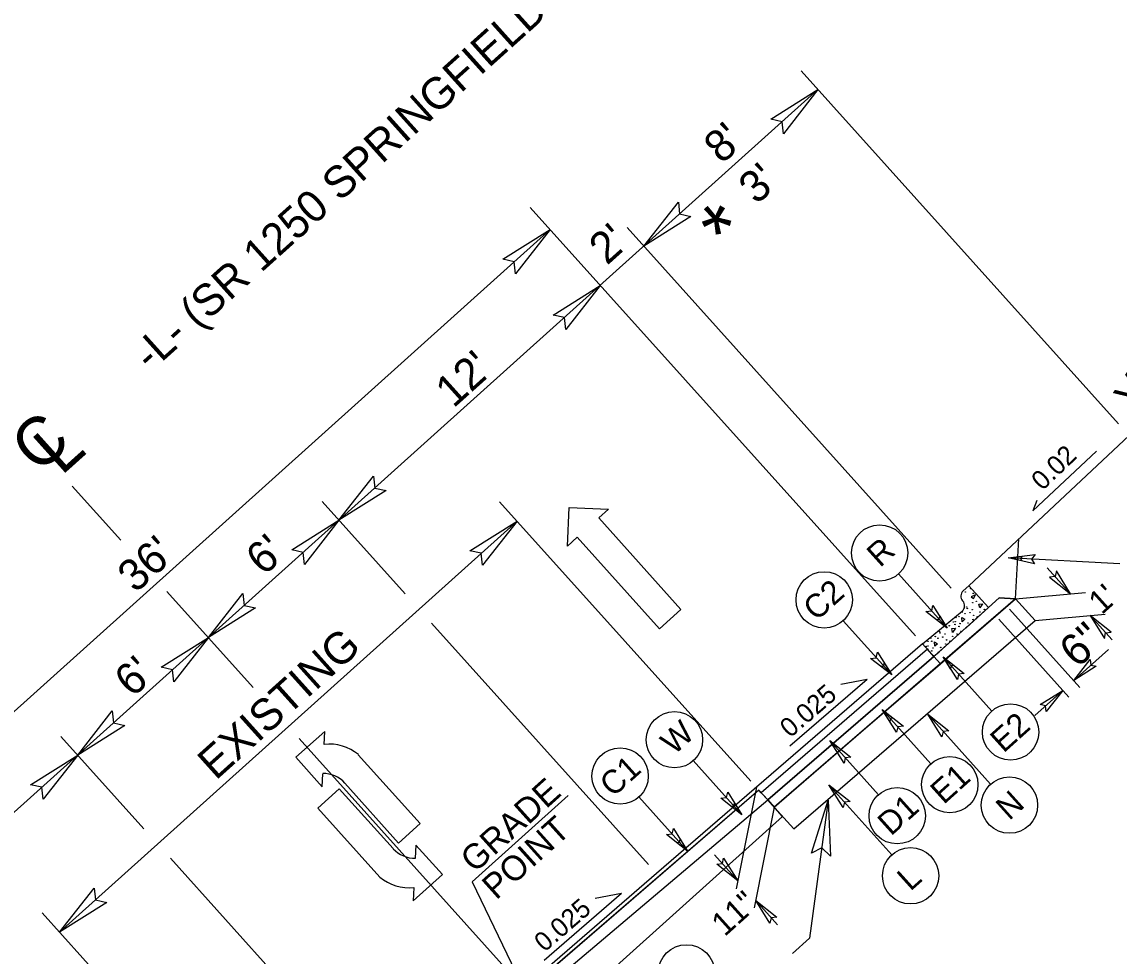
# Model space of a CAD drawing. Extents: x 2488411 to 2488707, y 383669 to 383962.
# Drawn here: x 2488564.63 to 2488602.08, y 383868.92 to 383900.82 of the extents above; entities that cross this region are included whole.
import ezdxf

# ---------------------------------------------------------------- set-up
doc = ezdxf.new("R2010")
doc.units = 0
for name, color, linetype in [('Old_Level_44', 7, 'Continuous'), ('Prop Dimension', 7, 'Continuous'), ('Prop DSN Text', 7, 'Continuous'), ('Prop Paint Stripe', 7, 'Continuous'), ('Prop PFL Text', 7, 'Continuous'), ('Prop Rip Rap Related Quantities Text', 7, 'Continuous'), ('Prop Roadway Profile Bench Mark Info Text', 7, 'Continuous'), ('Prop ROW RW Lines', 7, 'Continuous'), ('Prop Vertical Profile Curve Label', 7, 'Continuous'), ('Sheet Data Field CELL', 7, 'Continuous'), ('Sheet Sticker Preliminary CELL', 7, 'Continuous'), ('Sheet Symbology CELL', 7, 'Continuous'), ('Sheet Title CELL', 7, 'Continuous'), ('Typical Hinge Slope Arterial CELL', 7, 'Continuous'), ('Typical ID Circle CELL', 7, 'Continuous'), ('Typical Terminator CELL', 7, 'Continuous'), ('Typical Text ID Circle CELL', 7, 'Continuous')]:
    doc.layers.add(name, color=color, linetype=linetype)

msp = doc.modelspace()

# ---------------------------------------------------------------- linework, layer by layer
at = {"layer": 'Prop Dimension'}
for p, q in [((2488580.003, 383871.462), (2488583.276, 383874.404)), ((2488592.155, 383874.246), (2488591.519, 383869.531)), ((2488580.003, 383871.462), (2488581.754, 383867.821)), ((2488590.941, 383869.012), (2488591.519, 383869.531))]:
    msp.add_line(p, q, dxfattribs=at)
at = {"layer": 'Prop DSN Text'}
for p, q in [((2488602.106, 383882.32), (2488598.304, 383882.521)), ((2488594.554, 383881.97), (2488596.216, 383880.122)), ((2488592.662, 383880.369), (2488594.324, 383878.521)), ((2488597.739, 383877.287), (2488596.078, 383879.135)), ((2488595.662, 383875.49), (2488594.001, 383877.338)), ((2488597.699, 383874.791), (2488595.552, 383877.179)), ((2488593.87, 383874.429), (2488592.208, 383876.278)), ((2488587.549, 383875.594), (2488589.21, 383873.746)), ((2488594.325, 383872.379), (2488592.178, 383874.767)), ((2488585.692, 383874.355), (2488587.354, 383872.507))]:
    msp.add_line(p, q, dxfattribs=at)
for centre in [(2488593.911, 383882.685), (2488592.019, 383881.084), (2488586.906, 383876.309), (2488598.382, 383876.572), (2488585.049, 383875.07), (2488596.305, 383874.775), (2488598.342, 383874.076), (2488594.512, 383873.714), (2488594.968, 383871.664), (2488587.314, 383868.347)]:
    msp.add_circle(centre, 0.962, dxfattribs=at)
at = {"layer": 'Prop Paint Stripe'}
for points in [[(2488599.194, 383882.319), (2488598.304, 383882.521), (2488599.216, 383882.633), (2488599.093, 383882.479)], [(2488599.713, 383881.858), (2488600.43, 383881.292), (2488599.944, 383882.072), (2488599.902, 383881.88)], [(2488595.729, 383880.895), (2488596.216, 383880.122), (2488595.492, 383880.688), (2488595.687, 383880.709)], [(2488601.816, 383879.983), (2488601.099, 383880.548), (2488601.585, 383879.768), (2488601.627, 383879.961)], [(2488593.837, 383879.294), (2488594.324, 383878.521), (2488593.6, 383879.087), (2488593.795, 383879.108)], [(2488596.564, 383878.362), (2488596.078, 383879.135), (2488596.802, 383878.569), (2488596.606, 383878.548)], [(2488601.309, 383878.815), (2488600.536, 383878.329), (2488601.102, 383879.053), (2488601.124, 383878.857)], [(2488599.391, 383877.508), (2488600.164, 383877.995), (2488599.598, 383877.271), (2488599.577, 383877.466)], [(2488594.487, 383876.565), (2488594.001, 383877.338), (2488594.725, 383876.772), (2488594.529, 383876.751)], [(2488596.039, 383876.406), (2488595.552, 383877.179), (2488596.276, 383876.613), (2488596.08, 383876.591)], [(2488592.695, 383875.505), (2488592.208, 383876.278), (2488592.932, 383875.712), (2488592.736, 383875.69)], [(2488592.665, 383873.994), (2488592.178, 383874.767), (2488592.902, 383874.201), (2488592.706, 383874.18)], [(2488588.724, 383874.519), (2488589.21, 383873.746), (2488588.486, 383874.312), (2488588.682, 383874.333)], [(2488586.867, 383873.28), (2488587.354, 383872.507), (2488586.63, 383873.073), (2488586.826, 383873.095)], [(2488588.585, 383872.266), (2488589.071, 383871.493), (2488588.347, 383872.059), (2488588.543, 383872.081)], [(2488590.166, 383870.043), (2488589.68, 383870.816), (2488590.404, 383870.25), (2488590.208, 383870.229)]]:
    msp.add_lwpolyline(points, close=True, dxfattribs=at)
at = {"layer": 'Prop PFL Text'}
for p, q in [((2488599.144, 383884.129), (2488601.311, 383886.159)), ((2488599.279, 383884.472), (2488599.144, 383884.129))]:
    msp.add_line(p, q, dxfattribs=at)
at = {"layer": 'Prop Rip Rap Related Quantities Text'}
for p, q in [((2488598.554, 383881.124), (2488598.663, 383883.163)), ((2488598.554, 383881.124), (2488590.312, 383874.008)), ((2488597.996, 383881.154), (2488597.625, 383880.82)), ((2488597.996, 383881.154), (2488598.554, 383881.124)), ((2488598.554, 383881.124), (2488599.223, 383880.381)), ((2488590.981, 383873.264), (2488599.223, 383880.381)), ((2488595.376, 383879.582), (2488586.294, 383871.741)), ((2488595.543, 383879.396), (2488589.871, 383874.499)), ((2488595.764, 383879.151), (2488590.091, 383874.253)), ((2488595.766, 383879.149), (2488595.984, 383878.905)), ((2488589.787, 383874.592), (2488581.836, 383867.727)), ((2488590.091, 383874.253), (2488589.787, 383874.592)), ((2488590.312, 383874.008), (2488590.981, 383873.264)), ((2488586.294, 383871.741), (2488581.754, 383867.821))]:
    msp.add_line(p, q, dxfattribs=at)
at = {"layer": 'Prop Roadway Profile Bench Mark Info Text'}
for p, q in [((2488593.48, 383878.37), (2488590.84, 383876.091)), ((2488593.48, 383878.37), (2488592.581, 383878.198)), ((2488585.092, 383871.053), (2488582.452, 383868.775)), ((2488585.092, 383871.053), (2488584.193, 383870.882))]:
    msp.add_line(p, q, dxfattribs=at)
at = {"layer": 'Prop ROW RW Lines'}
for p, q in [((2488583.248, 383882.919), (2488583.308, 383884.244)), ((2488583.308, 383884.244), (2488584.654, 383884.183)), ((2488584.654, 383884.183), (2488584.319, 383883.882)), ((2488584.319, 383883.882), (2488587.127, 383880.758)), ((2488583.583, 383883.22), (2488583.248, 383882.919)), ((2488586.391, 383880.097), (2488583.583, 383883.22)), ((2488587.127, 383880.758), (2488586.391, 383880.097)), ((2488574.972, 383876.591), (2488573.98, 383875.719)), ((2488574.948, 383876.146), (2488574.972, 383876.591)), ((2488573.98, 383875.719), (2488574.872, 383874.705)), ((2488578.225, 383873.444), (2488576.109, 383875.797)), ((2488574.872, 383874.705), (2488574.895, 383875.15)), ((2488575.462, 383874.631), (2488574.726, 383873.97)), ((2488577.298, 383872.59), (2488575.462, 383874.631)), ((2488575.653, 383874.823), (2488577.488, 383872.782)), ((2488574.726, 383873.97), (2488576.842, 383871.616)), ((2488577.488, 383872.782), (2488578.225, 383873.444)), ((2488578.079, 383872.708), (2488578.056, 383872.263)), ((2488578.982, 383871.704), (2488578.079, 383872.708)), ((2488577.989, 383870.811), (2488578.982, 383871.704)), ((2488578.003, 383871.267), (2488577.989, 383870.811))]:
    msp.add_line(p, q, dxfattribs=at)
for centre, radius, start, end in [((2488575.113, 383874.583), 1.576, 50.6299, 95.9416), ((2488574.924, 383874.172), 0.982, 41.9538, 91.612), ((2488578.036, 383873.244), 0.982, 221.9538, 271.612), ((2488577.847, 383872.833), 1.576, 230.6299, 275.9416)]:
    msp.add_arc(centre, radius, start, end, dxfattribs=at)
at = {"layer": 'Prop Vertical Profile Curve Label'}
msp.add_line((2488596.956, 383881.563), (2488602.427, 383886.692), dxfattribs=at)
at = {"layer": 'Sheet Data Field CELL'}
for p, q in [((2488595.543, 383879.396), (2488589.871, 383874.499)), ((2488590.091, 383874.253), (2488595.764, 383879.151)), ((2488595.764, 383879.151), (2488595.543, 383879.396)), ((2488589.871, 383874.499), (2488590.091, 383874.253))]:
    msp.add_line(p, q, dxfattribs=at)
at = {"layer": 'Sheet Sticker Preliminary CELL'}
for points in [[(2488590.196, 383897.493), (2488591.806, 383898.506), (2488590.627, 383896.998), (2488590.583, 383897.406)], [(2488587.469, 383894.173), (2488585.859, 383893.16), (2488587.038, 383894.668), (2488587.083, 383894.26)], [(2488581.051, 383892.713), (2488582.661, 383893.727), (2488581.482, 383892.219), (2488581.437, 383892.627)], [(2488582.762, 383890.81), (2488584.372, 383891.823), (2488583.193, 383890.315), (2488583.148, 383890.723)], [(2488577.061, 383884.817), (2488575.451, 383883.804), (2488576.63, 383885.312), (2488576.675, 383884.904)], [(2488573.841, 383882.791), (2488575.451, 383883.804), (2488574.272, 383882.296), (2488574.227, 383882.704)], [(2488579.92, 383882.763), (2488581.53, 383883.777), (2488580.351, 383882.269), (2488580.307, 383882.677)], [(2488598.768, 383882.416), (2488598.304, 383882.521), (2488598.779, 383882.58), (2488598.715, 383882.499)], [(2488572.601, 383880.808), (2488570.991, 383879.795), (2488572.17, 383881.303), (2488572.215, 383880.895)], [(2488595.962, 383880.524), (2488596.216, 383880.122), (2488595.839, 383880.417), (2488595.941, 383880.428)], [(2488569.381, 383878.782), (2488570.991, 383879.795), (2488569.812, 383878.287), (2488569.767, 383878.695)], [(2488596.331, 383878.733), (2488596.078, 383879.135), (2488596.455, 383878.84), (2488596.353, 383878.829)], [(2488594.07, 383878.923), (2488594.324, 383878.521), (2488593.947, 383878.816), (2488594.049, 383878.827)], [(2488568.141, 383876.799), (2488566.531, 383875.786), (2488567.71, 383877.294), (2488567.755, 383876.886)], [(2488594.254, 383876.936), (2488594.001, 383877.338), (2488594.378, 383877.044), (2488594.276, 383877.032)], [(2488564.921, 383874.772), (2488566.531, 383875.786), (2488565.352, 383874.277), (2488565.308, 383874.685)], [(2488591.584, 383872.431), (2488592.155, 383874.246), (2488592.233, 383872.333), (2488591.935, 383872.615)], [(2488588.957, 383874.148), (2488589.21, 383873.746), (2488588.833, 383874.041), (2488588.935, 383874.052)], [(2488587.1, 383872.91), (2488587.354, 383872.507), (2488586.977, 383872.802), (2488587.079, 383872.813)], [(2488567.523, 383870.751), (2488565.913, 383869.738), (2488567.092, 383871.246), (2488567.137, 383870.838)]]:
    msp.add_lwpolyline(points, close=True, dxfattribs=at)
at = {"layer": 'Sheet Symbology CELL'}
for p, q in [((2488595.984, 383878.905), (2488598.554, 383881.124)), ((2488597.996, 383881.154), (2488597.625, 383880.82)), ((2488598.554, 383881.124), (2488597.996, 383881.154)), ((2488597.625, 383880.82), (2488596.863, 383880.135)), ((2488595.764, 383879.151), (2488590.091, 383874.253)), ((2488595.766, 383879.149), (2488595.764, 383879.151)), ((2488595.766, 383879.149), (2488595.984, 383878.905)), ((2488595.984, 383878.905), (2488595.766, 383879.149)), ((2488593.274, 383876.565), (2488595.984, 383878.905)), ((2488590.312, 383874.008), (2488593.274, 383876.565)), ((2488593.274, 383876.565), (2488593.274, 383876.565)), ((2488589.871, 383874.499), (2488589.787, 383874.592)), ((2488582.065, 383867.476), (2488590.091, 383874.253)), ((2488590.091, 383874.253), (2488589.871, 383874.499)), ((2488590.091, 383874.253), (2488590.312, 383874.008))]:
    msp.add_line(p, q, dxfattribs=at)
for points in [[(2488596.855, 383880.128), (2488596.855, 383880.128), (2488595.934, 383879.3)], [(2488595.926, 383879.293), (2488595.926, 383879.293), (2488595.766, 383879.149)], [(2488593.274, 383876.565), (2488593.274, 383876.565)], [(2488589.787, 383874.592), (2488581.84, 383867.73), (2488581.838, 383867.728)]]:
    msp.add_lwpolyline(points, dxfattribs=at)
for centre in [(2488596.855, 383880.136), (2488595.926, 383879.301)]:
    msp.add_arc(centre, 0.00802, 270.1633, 353.7444, dxfattribs=at)
at = {"layer": 'Sheet Title CELL'}
for p, q in [((2488602.065, 383887.095), (2488591.234, 383899.144)), ((2488550.176, 383861.083), (2488591.806, 383898.506)), ((2488595.131, 383879.855), (2488581.981, 383894.483)), ((2488555.899, 383869.669), (2488582.661, 383893.727)), ((2488596.352, 383881.487), (2488585.286, 383893.797)), ((2488577.711, 383881.29), (2488574.878, 383884.441)), ((2488589.514, 383874.895), (2488580.937, 383884.437)), ((2488565.913, 383869.738), (2488581.53, 383883.777)), ((2488600.43, 383881.292), (2488599.635, 383882.177)), ((2488598.554, 383881.124), (2488600.944, 383881.338)), ((2488597.625, 383880.82), (2488597.625, 383880.82)), ((2488600.746, 383878.095), (2488598.348, 383880.763)), ((2488599.223, 383880.381), (2488601.612, 383880.594)), ((2488601.846, 383879.717), (2488601.099, 383880.548)), ((2488586.022, 383872.045), (2488578.614, 383880.285)), ((2488600.374, 383877.761), (2488597.976, 383880.429)), ((2488600.536, 383878.329), (2488601.721, 383879.394)), ((2488599.212, 383877.139), (2488600.164, 383877.995)), ((2488568.792, 383873.271), (2488565.959, 383876.423)), ((2488589.704, 383874.685), (2488589.017, 383871.22)), ((2488590.312, 383874.008), (2488589.63, 383870.564)), ((2488589.071, 383871.493), (2488588.276, 383872.378)), ((2488577.04, 383864.096), (2488569.694, 383872.267)), ((2488590.427, 383869.985), (2488589.68, 383870.816)), ((2488573.76, 383861.008), (2488565.32, 383870.397))]:
    msp.add_line(p, q, dxfattribs=at)
at = {"layer": 'Typical ID Circle CELL'}
for p, q in [((2488596.956, 383881.563), (2488596.763, 383881.389)), ((2488597.625, 383880.82), (2488596.956, 383881.563)), ((2488596.752, 383881.043), (2488596.745, 383881.051)), ((2488597.182, 383881.258), (2488597.037, 383881.188)), ((2488597.037, 383881.188), (2488597.11, 383881.132)), ((2488597.11, 383881.132), (2488597.182, 383881.258)), ((2488597.301, 383880.936), (2488597.428, 383880.95)), ((2488597.331, 383880.809), (2488597.301, 383880.936)), ((2488597.428, 383880.95), (2488597.331, 383880.809)), ((2488595.376, 383879.582), (2488596.726, 383880.698)), ((2488597.625, 383880.82), (2488595.766, 383879.149)), ((2488596.729, 383880.336), (2488596.712, 383880.483)), ((2488596.712, 383880.483), (2488596.814, 383880.421)), ((2488596.814, 383880.421), (2488596.729, 383880.336)), ((2488596.373, 383880.102), (2488596.499, 383880.115)), ((2488596.403, 383879.975), (2488596.373, 383880.102)), ((2488596.499, 383880.115), (2488596.403, 383879.975)), ((2488595.766, 383879.149), (2488595.376, 383879.582)), ((2488595.799, 383879.501), (2488595.783, 383879.648)), ((2488595.783, 383879.648), (2488595.885, 383879.586)), ((2488595.885, 383879.586), (2488595.799, 383879.501))]:
    msp.add_line(p, q, dxfattribs=at)
for centre in [(2488596.836, 383881.353), (2488597.02, 383881.472), (2488597.104, 383881.302), (2488597.091, 383880.992), (2488597.214, 383881.034), (2488596.738, 383880.667), (2488596.828, 383880.61), (2488596.881, 383880.841), (2488596.902, 383880.792), (2488596.995, 383880.646), (2488597.07, 383880.751), (2488597.124, 383880.554), (2488597.332, 383880.672), (2488597.486, 383880.757), (2488596.285, 383880.199), (2488596.43, 383880.329), (2488596.482, 383880.245), (2488596.494, 383880.341), (2488596.519, 383880.475), (2488596.619, 383880.177), (2488596.62, 383880.508), (2488596.66, 383880.276), (2488596.928, 383880.294), (2488597.096, 383880.414), (2488597.243, 383880.507), (2488595.81, 383879.832), (2488595.952, 383880.006), (2488595.973, 383879.957), (2488596.066, 383879.811), (2488596.141, 383879.916), (2488596.162, 383880.157), (2488596.403, 383879.837), (2488596.557, 383879.922), (2488596.683, 383880.012), (2488596.855, 383880.136), (2488595.501, 383879.494), (2488595.562, 383879.671), (2488595.565, 383879.506), (2488595.657, 383879.779), (2488595.691, 383879.673), (2488595.731, 383879.441), (2488595.899, 383879.775), (2488595.999, 383879.459), (2488596.167, 383879.579), (2488596.195, 383879.719), (2488596.314, 383879.672), (2488595.553, 383879.41), (2488595.691, 383879.342), (2488595.755, 383879.177), (2488595.926, 383879.301)]:
    msp.add_circle(centre, 0.00802, dxfattribs=at)
for centre, start, end in [((2488596.923, 383881.211), 131.9538, 221.9538), ((2488596.574, 383880.883), 309.5694, 41.9538)]:
    msp.add_arc(centre, 0.24, start, end, dxfattribs=at)
at = {"layer": 'Typical Terminator CELL'}
for p, q in [((2488568, 383883.122), (2488566.34, 383884.968)), ((2488572.518, 383878.096), (2488569.578, 383881.367)), ((2488583.758, 383865.593), (2488574.09, 383876.348))]:
    msp.add_line(p, q, dxfattribs=at)
at = {"layer": 'Typical Text ID Circle CELL'}
for p, q in [((2488582.065, 383867.476), (2488590.091, 383874.253)), ((2488590.597, 383873.691), (2488590.091, 383874.253)), ((2488574.979, 383859.652), (2488590.597, 383873.691))]:
    msp.add_line(p, q, dxfattribs=at)

# ---------------------------------------------------------------- texts
at = {"layer": 'Old_Level_44'}
for s, p in [('R', (2488593.924, 383882.165)), ('C2', (2488591.751, 383880.334)), ('E2', (2488598.14, 383875.834)), ('W', (2488586.888, 383875.76)), ('C1', (2488584.803, 383874.321)), ('E1', (2488596.096, 383874.076)), ('N', (2488598.334, 383873.526)), ('D1', (2488594.295, 383872.999)), ('L', (2488594.96, 383871.114))]:
    msp.add_text(s, height=0.8, rotation=41.9538, dxfattribs=at).set_placement(p)
at = {"layer": 'Prop Dimension'}
for s, p in [('GRADE', (2488580.081, 383871.735)), ('POINT', (2488580.819, 383870.814))]:
    msp.add_text(s, height=0.85, rotation=41.9538, dxfattribs=at).set_placement(p)
at = {"layer": 'Prop PFL Text'}
msp.add_text('0.02 ', height=0.6476, rotation=43.7622, dxfattribs=at).set_placement((2488599.468, 383884.79))
at = {"layer": 'Prop Roadway Profile Bench Mark Info Text'}
for s, height, rotation, p in [('VAR. (3:1 MAX)', 1, 55.9901, (2488602.696, 383887.584)), ('0.025', 0.6476, 40.8081, (2488590.855, 383876.351)), ('0.025', 0.6476, 40.8081, (2488582.467, 383869.035))]:
    msp.add_text(s, height=height, rotation=rotation, dxfattribs=at).set_placement(p)
at = {"layer": 'Sheet Title CELL'}
for s, height, p in [('-L- (SR 1250 SPRINGFIELD RD)', 1.0817, (2488569.025, 383888.853)), ("8'", 1.0817, (2488588.521, 383895.94)), ("3'", 1.0817, (2488589.708, 383894.555)), ('*', 2, (2488588.92, 383892.642)), ("2'", 1.0817, (2488584.601, 383892.487)), ("12'", 1.0817, (2488579.358, 383887.61)), ("36'", 1.0817, (2488568.505, 383881.292)), ("6'", 1.0817, (2488572.887, 383881.879)), ("1'", 0.8, (2488601.493, 383880.556)), ('6"', 1.0817, (2488600.661, 383878.722)), ('EXISTING', 1.0817, (2488571.244, 383874.9)), ("6'", 1.0817, (2488568.4, 383877.723)), ('11"', 0.8, (2488588.619, 383869.565))]:
    msp.add_text(s, height=height, rotation=41.9538, dxfattribs=at).set_placement(p)
at = {"layer": 'Typical Hinge Slope Arterial CELL'}
for s, height, rotation, p in [('C', 1.64, 41.9538, (2488565.192, 383885.354)), ('L', 1.641, 41.9007, (2488565.972, 383885.303))]:
    msp.add_text(s, height=height, rotation=rotation, dxfattribs=at).set_placement(p)

doc.saveas('drawing.dxf')
